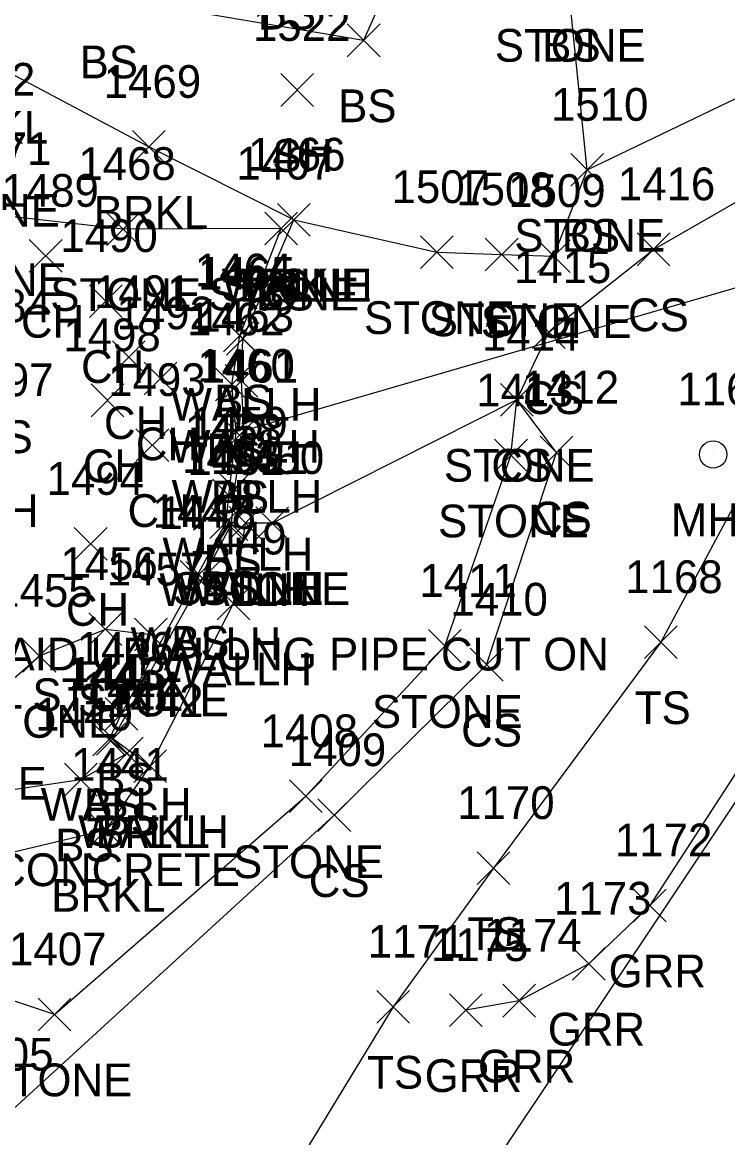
# Model space of a CAD drawing. Extents: x 1599840 to 1601211, y 518904 to 521989.
# Drawn here: x 1600771.9 to 1600815, y 521246 to 521314.2 of the extents above; entities that cross this region are included whole.
import ezdxf

# ---------------------------------------------------------------- set-up
doc = ezdxf.new("R2010")
doc.units = 0
for name, color, linetype in [('D_A', 7, 'Continuous'), ('D_C', 7, 'Continuous'), ('D_I', 7, 'Continuous'), ('D_TIC', 7, 'Continuous'), ('DCP', 7, 'Continuous'), ('DHW', 7, 'Continuous'), ('L_A', 7, 'Continuous'), ('L_C', 7, 'Continuous'), ('L_I', 7, 'Continuous'), ('L_TIC', 7, 'Continuous'), ('LASF', 7, 'Continuous'), ('LAWE', 7, 'Continuous'), ('LELB', 7, 'Continuous'), ('PET', 7, 'Continuous'), ('R_A', 7, 'Continuous'), ('R_I', 7, 'Continuous'), ('R_TIC', 7, 'Continuous'), ('RGR', 7, 'Continuous'), ('U_A', 7, 'Continuous'), ('U_I', 7, 'Continuous'), ('USMH', 7, 'Continuous')]:
    doc.layers.add(name, color=color, linetype=linetype)

msp = doc.modelspace()

# ---------------------------------------------------------------- linework, layer by layer
at = {"layer": 'D_TIC'}
for points in [[(1600787.504, 521301.133), (1600789.504, 521303.133)], [(1600789.504, 521301.133), (1600787.504, 521303.133)], [(1600784.387, 521293.849), (1600786.387, 521295.849)], [(1600786.387, 521293.849), (1600784.387, 521295.849)], [(1600784.3, 521291.284), (1600786.3, 521293.284)], [(1600786.3, 521291.284), (1600784.3, 521293.284)], [(1600784.444, 521288.23), (1600786.444, 521290.23)], [(1600786.444, 521288.23), (1600784.444, 521290.23)], [(1600784.444, 521288.23), (1600786.444, 521290.23)], [(1600786.444, 521288.23), (1600784.444, 521290.23)], [(1600783.887, 521284.699), (1600785.887, 521286.699)], [(1600785.887, 521284.699), (1600783.887, 521286.699)], [(1600783.695, 521282.537), (1600785.695, 521284.537)], [(1600785.695, 521282.537), (1600783.695, 521284.537)], [(1600784.559, 521282.602), (1600786.559, 521284.602)], [(1600786.559, 521282.602), (1600784.559, 521284.602)], [(1600781.935, 521279.231), (1600783.935, 521281.231)], [(1600783.935, 521279.231), (1600781.935, 521281.231)], [(1600783.815, 521277.679), (1600785.815, 521279.679)], [(1600785.815, 521277.679), (1600783.815, 521279.679)], [(1600776.448, 521269.418), (1600778.448, 521271.418)], [(1600778.448, 521269.418), (1600776.448, 521271.418)], [(1600778.729, 521267.746), (1600780.729, 521269.746)], [(1600780.729, 521267.746), (1600778.729, 521269.746)], [(1600778.729, 521267.746), (1600780.729, 521269.746)], [(1600780.729, 521267.746), (1600778.729, 521269.746)]]:
    msp.add_lwpolyline(points, dxfattribs=at)
at = {"layer": 'DCP'}
msp.add_lwpolyline([(1600954.732, 521338.43), (1600785.444, 521289.23)], dxfattribs=at)
at = {"layer": 'DHW'}
for points in [[(1600779.729, 521268.746), (1600777.448, 521270.418), (1600782.935, 521280.231), (1600784.695, 521283.537), (1600784.887, 521285.699), (1600785.444, 521289.23), (1600785.3, 521292.284), (1600785.387, 521294.849), (1600788.504, 521302.133)], [(1600779.729, 521268.746), (1600784.815, 521278.679), (1600785.559, 521283.602)]]:
    msp.add_lwpolyline(points, dxfattribs=at)
at = {"layer": 'L_TIC'}
for points in [[(1600791.769, 521312.092), (1600793.769, 521314.092)], [(1600793.769, 521312.092), (1600791.769, 521314.092)], [(1600787.702, 521309.057), (1600789.702, 521311.057)], [(1600789.702, 521309.057), (1600787.702, 521311.057)], [(1600778.639, 521305.578), (1600780.639, 521307.578)], [(1600780.639, 521305.578), (1600778.639, 521307.578)], [(1600805.428, 521304.176), (1600807.428, 521306.176)], [(1600807.428, 521304.176), (1600805.428, 521306.176)], [(1600805.428, 521304.176), (1600807.428, 521306.176)], [(1600807.428, 521304.176), (1600805.428, 521306.176)], [(1600787.504, 521301.133), (1600789.504, 521303.133)], [(1600789.504, 521301.133), (1600787.504, 521303.133)], [(1600787.504, 521301.133), (1600789.504, 521303.133)], [(1600789.504, 521301.133), (1600787.504, 521303.133)], [(1600777.08, 521300.561), (1600779.08, 521302.561)], [(1600779.08, 521300.561), (1600777.08, 521302.561)], [(1600786.733, 521300.588), (1600788.733, 521302.588)], [(1600788.733, 521300.588), (1600786.733, 521302.588)], [(1600786.733, 521300.588), (1600788.733, 521302.588)], [(1600788.733, 521300.588), (1600786.733, 521302.588)], [(1600772.345, 521298.923), (1600774.345, 521300.923)], [(1600774.345, 521298.923), (1600772.345, 521300.923)], [(1600796.248, 521299.149), (1600798.248, 521301.149)], [(1600798.248, 521299.149), (1600796.248, 521301.149)], [(1600800.203, 521299.015), (1600802.203, 521301.015)], [(1600802.203, 521299.015), (1600800.203, 521301.015)], [(1600803.381, 521298.912), (1600805.381, 521300.912)], [(1600805.381, 521298.912), (1600803.381, 521300.912)], [(1600809.479, 521299.323), (1600811.479, 521301.323)], [(1600811.479, 521299.323), (1600809.479, 521301.323)], [(1600776.018, 521296.16), (1600778.018, 521298.16)], [(1600778.018, 521296.16), (1600776.018, 521298.16)], [(1600803.075, 521294.258), (1600805.075, 521296.258)], [(1600805.075, 521294.258), (1600803.075, 521296.258)], [(1600784.198, 521294.053), (1600786.198, 521296.053)], [(1600786.198, 521294.053), (1600784.198, 521296.053)], [(1600777.417, 521292.732), (1600779.417, 521294.732)], [(1600779.417, 521292.732), (1600777.417, 521294.732)], [(1600779.364, 521291.436), (1600781.364, 521293.436)], [(1600781.364, 521291.436), (1600779.364, 521293.436)], [(1600783.719, 521291.066), (1600785.719, 521293.066)], [(1600785.719, 521291.066), (1600783.719, 521293.066)], [(1600776.119, 521290.098), (1600778.119, 521292.098)], [(1600778.119, 521290.098), (1600776.119, 521292.098)], [(1600801.128, 521290.126), (1600803.128, 521292.126)], [(1600803.128, 521290.126), (1600801.128, 521292.126)], [(1600801.128, 521290.126), (1600803.128, 521292.126)], [(1600803.128, 521290.126), (1600801.128, 521292.126)], [(1600783.988, 521288.181), (1600785.988, 521290.181)], [(1600785.988, 521288.181), (1600783.988, 521290.181)], [(1600778.858, 521287.36), (1600780.858, 521289.36)], [(1600780.858, 521287.36), (1600778.858, 521289.36)], [(1600800.771, 521286.725), (1600802.771, 521288.725)], [(1600802.771, 521286.725), (1600800.771, 521288.725)], [(1600803.556, 521286.901), (1600805.556, 521288.901)], [(1600805.556, 521286.901), (1600803.556, 521288.901)], [(1600783.535, 521284.275), (1600785.535, 521286.275)], [(1600785.535, 521284.275), (1600783.535, 521286.275)], [(1600783.373, 521282.656), (1600785.373, 521284.656)], [(1600785.373, 521282.656), (1600783.373, 521284.656)], [(1600784.559, 521282.602), (1600786.559, 521284.602)], [(1600786.559, 521282.602), (1600784.559, 521284.602)], [(1600786.187, 521282.594), (1600788.187, 521284.594)], [(1600788.187, 521282.594), (1600786.187, 521284.594)], [(1600775.092, 521281.323), (1600777.092, 521283.323)], [(1600777.092, 521281.323), (1600775.092, 521283.323)], [(1600781.563, 521279.311), (1600783.563, 521281.311)], [(1600783.563, 521279.311), (1600781.563, 521281.311)], [(1600775.99, 521276.111), (1600777.99, 521278.111)], [(1600777.99, 521276.111), (1600775.99, 521278.111)], [(1600778.773, 521275.79), (1600780.773, 521277.79)], [(1600780.773, 521275.79), (1600778.773, 521277.79)], [(1600796.728, 521275.088), (1600798.728, 521277.088)], [(1600798.728, 521275.088), (1600796.728, 521277.088)], [(1600809.924, 521275.319), (1600811.924, 521277.319)], [(1600811.924, 521275.319), (1600809.924, 521277.319)], [(1600771.957, 521274.482), (1600773.957, 521276.482)], [(1600773.957, 521274.482), (1600771.957, 521276.482)], [(1600799.284, 521273.946), (1600801.284, 521275.946)], [(1600801.284, 521273.946), (1600799.284, 521275.946)], [(1600776.984, 521270.944), (1600778.984, 521272.944)], [(1600778.984, 521270.944), (1600776.984, 521272.944)], [(1600776.22, 521269.369), (1600778.22, 521271.369)], [(1600778.22, 521269.369), (1600776.22, 521271.369)], [(1600777.299, 521268.516), (1600779.299, 521270.516)], [(1600779.299, 521268.516), (1600777.299, 521270.516)], [(1600778.729, 521267.746), (1600780.729, 521269.746)], [(1600780.729, 521267.746), (1600778.729, 521269.746)], [(1600774.487, 521266.923), (1600776.487, 521268.923)], [(1600776.487, 521266.923), (1600774.487, 521268.923)], [(1600788.245, 521265.906), (1600790.245, 521267.906)], [(1600790.245, 521265.906), (1600788.245, 521267.906)], [(1600789.977, 521264.75), (1600791.977, 521266.75)], [(1600791.977, 521264.75), (1600789.977, 521266.75)], [(1600776.034, 521263.853), (1600778.034, 521265.853)], [(1600778.034, 521263.853), (1600776.034, 521265.853)], [(1600799.695, 521261.518), (1600801.695, 521263.518)], [(1600801.695, 521261.518), (1600799.695, 521263.518)], [(1600772.881, 521252.578), (1600774.881, 521254.578)], [(1600774.881, 521252.578), (1600772.881, 521254.578)], [(1600772.881, 521252.578), (1600774.881, 521254.578)], [(1600774.881, 521252.578), (1600772.881, 521254.578)], [(1600793.575, 521253.044), (1600795.575, 521255.044)], [(1600795.575, 521253.044), (1600793.575, 521255.044)]]:
    msp.add_lwpolyline(points, dxfattribs=at)
at = {"layer": 'LASF'}
for points in [[(1600788.504, 521302.133), (1600797.248, 521300.149), (1600801.203, 521300.015), (1600804.381, 521299.912), (1600806.428, 521305.176), (1600805.239, 521316.786), (1600796.978, 521329.204), (1600794.865, 521329.922), (1600789.19, 521328.403), (1600773.997, 521324.831), (1600760.497, 521319.404), (1600745.632, 521315.291), (1600743.26, 521323.098), (1600732.014, 521314.218), (1600727.669, 521298.755)], [(1600787.733, 521301.588), (1600778.08, 521301.561), (1600769.876, 521302.473), (1600769.452, 521306.712), (1600761.198, 521309.066), (1600753.437, 521305.807), (1600746.621, 521300.165), (1600732.332, 521294.559), (1600731.017, 521295.657), (1600727.669, 521298.755)], [(1600773.881, 521253.578), (1600789.245, 521266.906), (1600797.728, 521276.088), (1600801.771, 521287.725), (1600802.128, 521291.126), (1600787.187, 521283.594), (1600785.559, 521283.602)], [(1600773.881, 521253.578), (1600761.877, 521257.582), (1600761.441, 521259.849), (1600764.145, 521267.439), (1600768.657, 521271.705), (1600772.957, 521275.482), (1600776.99, 521277.111), (1600779.773, 521276.79)]]:
    msp.add_lwpolyline(points, dxfattribs=at)
at = {"layer": 'LAWE'}
for points in [[(1600788.504, 521302.133), (1600779.639, 521306.578), (1600769.853, 521311.777), (1600761.009, 521310.636), (1600751.785, 521307.227), (1600745.14, 521302.726), (1600731.017, 521295.657), (1600729.255, 521276.143), (1600716.099, 521262.819), (1600704.876, 521257.404), (1600692.678, 521234.473)], [(1600710.084, 521218.612), (1600728.191, 521240.002), (1600744.345, 521252.061), (1600761.877, 521257.582), (1600767.454, 521262.572), (1600777.034, 521264.853), (1600779.729, 521268.746)]]:
    msp.add_lwpolyline(points, dxfattribs=at)
at = {"layer": 'LELB'}
for points in [[(1600796.978, 521329.204), (1600795.834, 521320.03), (1600792.769, 521313.092), (1600776.979, 521315.771), (1600787.857, 521318.753), (1600792.84, 521323.569), (1600794.865, 521329.922)], [(1600806.428, 521305.176), (1600817.079, 521310.295), (1600825.263, 521317.394), (1600823.051, 521319.829), (1600819.351, 521326.934), (1600812.796, 521319.539), (1600805.239, 521316.786)], [(1600833.084, 521322.836), (1600827.139, 521306.559), (1600810.924, 521276.319), (1600800.695, 521262.518), (1600794.575, 521254.044), (1600785.727, 521239.523), (1600767.248, 521213.824), (1600747.487, 521193.493), (1600721.354, 521163.12)], [(1600741.132, 521196.942), (1600761.003, 521225.763), (1600770.642, 521247.145), (1600790.977, 521265.75), (1600800.284, 521274.946), (1600804.556, 521287.901), (1600802.128, 521291.126), (1600804.075, 521295.258), (1600810.479, 521300.323), (1600825.075, 521308.704)], [(1600708.733, 521220.076), (1600727.282, 521240.92), (1600743.422, 521252.915), (1600761.441, 521259.849), (1600767.997, 521266.834), (1600775.487, 521267.923), (1600778.299, 521269.516), (1600777.22, 521270.369), (1600777.984, 521271.944), (1600782.563, 521280.311), (1600784.373, 521283.656), (1600784.535, 521285.275), (1600784.988, 521289.181), (1600784.719, 521292.066), (1600785.198, 521295.053), (1600787.733, 521301.588)]]:
    msp.add_lwpolyline(points, dxfattribs=at)
at = {"layer": 'PET'}
msp.add_lwpolyline([(1600925.829, 521507.518), (1600915.18, 521473.309), (1600903.262, 521440.284), (1600887.481, 521401.444), (1600873.353, 521370.155), (1600860.378, 521343.642), (1600847.931, 521319.686), (1600844.651, 521313.138), (1600836.724, 521299.896), (1600818.79, 521271.507), (1600793.687, 521233.92), (1600774.487, 521208.057), (1600757.089, 521185.54), (1600730.915, 521154.494)], dxfattribs=at)
at = {"layer": 'R_TIC'}
for points in [[(1600809.245, 521259.238), (1600811.245, 521261.238)], [(1600811.245, 521259.238), (1600809.245, 521261.238)], [(1600805.532, 521255.677), (1600807.532, 521257.677)], [(1600807.532, 521255.677), (1600805.532, 521257.677)], [(1600801.263, 521253.419), (1600803.263, 521255.419)], [(1600803.263, 521253.419), (1600801.263, 521255.419)], [(1600798.012, 521252.838), (1600800.012, 521254.838)], [(1600800.012, 521252.838), (1600798.012, 521254.838)]]:
    msp.add_lwpolyline(points, dxfattribs=at)
at = {"layer": 'RGR'}
msp.add_lwpolyline([(1600826.087, 521344.206), (1600833.693, 521339.744), (1600838.119, 521335.633), (1600842.433, 521329.401), (1600844.673, 521324.013), (1600844.997, 521318.731), (1600843.514, 521313.735), (1600835.628, 521300.635), (1600817.836, 521271.897), (1600810.245, 521260.238), (1600806.532, 521256.677), (1600802.263, 521254.419), (1600799.012, 521253.838)], dxfattribs=at)
at = {"layer": 'USMH'}
for p, q in [((1600814.12, 521287.795), (1600814.12, 521287.795)), ((1600814.953, 521287.795), (1600814.953, 521287.795))]:
    msp.add_line(p, q, dxfattribs=at)
msp.add_circle((1600814.12, 521287.795), 0.833, dxfattribs=at)

# ---------------------------------------------------------------- texts
at = {"layer": 'D_A'}
for s, p in [('WALLH', (1600784.095, 521297.133)), ('WALLH', (1600780.977, 521289.849)), ('WALLH', (1600780.89, 521287.284)), ('WALLH', (1600781.034, 521284.23)), ('P', (1600784.822, 521284.23)), ('WALLH', (1600780.478, 521280.699)), ('WALLH', (1600780.286, 521278.537)), ('WALLH', (1600781.15, 521278.602)), ('WALLH', (1600778.526, 521275.231)), ('WALLH', (1600780.406, 521273.679)), ('WALLH', (1600773.039, 521265.418)), ('WALLH', (1600775.319, 521263.746)), ('WALLH', (1600775.319, 521263.746))]:
    msp.add_text(s, height=2, dxfattribs=at).set_placement(p)
at = {"layer": 'D_C'}
msp.add_text('CONCRETE', height=2, dxfattribs=at).set_placement((1600770.204, 521261.418))
at = {"layer": 'D_I'}
for s, p in [('1466', (1600785.709, 521305.133)), ('1465', (1600782.647, 521297.849)), ('1463', (1600782.56, 521295.284)), ('1460', (1600782.617, 521292.23)), ('1460', (1600782.617, 521292.23)), ('1459', (1600782.186, 521288.699)), ('1451', (1600783.433, 521286.602)), ('1452', (1600782.003, 521286.537)), ('1448', (1600780.242, 521283.231)), ('1449', (1600782.115, 521281.679)), ('1443', (1600774.755, 521273.418)), ('1442', (1600777.036, 521271.746)), ('1442', (1600777.036, 521271.746))]:
    msp.add_text(s, height=2, dxfattribs=at).set_placement(p)
at = {"layer": 'L_A'}
for s, p in [('BS', (1600786.298, 521313.753)), ('STONE', (1600800.782, 521311.786)), ('BS', (1600803.679, 521311.786)), ('BS', (1600775.42, 521310.771)), ('BS', (1600791.21, 521308.092)), ('BRKL', (1600766.499, 521306.777)), ('SH', (1600787.19, 521305.057)), ('STONE', (1600764.996, 521301.712)), ('BRKL', (1600776.285, 521301.578)), ('STONE', (1600801.971, 521300.176)), ('BS', (1600804.869, 521300.176)), ('STONE', (1600765.419, 521297.473)), ('STONE', (1600784.048, 521297.133)), ('BRKL', (1600785.15, 521297.133)), ('STONE', (1600773.623, 521296.561)), ('STONE', (1600783.277, 521296.588)), ('BS', (1600786.174, 521296.588)), ('CH', (1600771.833, 521294.923)), ('STONE', (1600792.791, 521295.149)), ('STONE', (1600796.746, 521295.015)), ('STONE', (1600799.925, 521294.912)), ('CS', (1600808.92, 521295.323)), ('CH', (1600775.507, 521292.16)), ('BS', (1600783.639, 521290.053)), ('CS', (1600802.516, 521290.258)), ('CH', (1600776.905, 521288.732)), ('CS', (1600768.84, 521287.873)), ('CH', (1600778.853, 521287.436)), ('BS', (1600783.16, 521287.066)), ('CH', (1600775.607, 521286.098)), ('STONE', (1600797.671, 521286.126)), ('CS', (1600800.568, 521286.126)), ('BS', (1600783.429, 521284.181)), ('CH', (1600769.057, 521283.355)), ('CH', (1600778.346, 521283.36)), ('STONE', (1600797.314, 521282.725)), ('CS', (1600802.997, 521282.901)), ('BS', (1600782.976, 521280.275)), ('STONE', (1600781.102, 521278.602)), ('STONE', (1600782.73, 521278.594)), ('BS', (1600782.814, 521278.656)), ('CH', (1600774.58, 521277.323)), ('BS', (1600781.004, 521275.311)), ('STONE', (1600772.533, 521272.111)), ('STONE', (1600775.316, 521271.79)), ('STONE', (1600793.272, 521271.088)), ('TS', (1600809.333, 521271.319)), ('STONE', (1600768.5, 521270.482)), ('CS', (1600798.725, 521269.946)), ('BS', (1600776.425, 521266.944)), ('STONE', (1600764.2, 521266.705)), ('BS', (1600775.661, 521265.369)), ('BS', (1600776.74, 521264.516)), ('BRKL', (1600776.374, 521263.746)), ('BS', (1600773.928, 521262.923)), ('STONE', (1600784.789, 521261.906)), ('CS', (1600789.418, 521260.75)), ('BRKL', (1600773.679, 521259.853)), ('TS', (1600799.104, 521257.518)), ('STONE', (1600769.424, 521248.578)), ('STONE', (1600769.424, 521248.578)), ('TS', (1600792.985, 521249.044))]:
    msp.add_text(s, height=2, dxfattribs=at).set_placement(p)
at = {"layer": 'L_C'}
msp.add_text('STONE LAID UP ALONG PIPE CUT ON', height=2, dxfattribs=at).set_placement((1600759.447, 521274.594))
at = {"layer": 'L_I'}
for s, p in [('1522', (1600786.009, 521313.057)), ('1472', (1600766.76, 521309.712)), ('1469', (1600776.892, 521309.578)), ('1510', (1600804.215, 521308.176)), ('1510', (1600804.215, 521308.176)), ('1471', (1600767.75, 521305.473)), ('1466', (1600785.709, 521305.133)), ('1466', (1600785.709, 521305.133)), ('1468', (1600775.34, 521304.561)), ('1467', (1600784.993, 521304.588)), ('1467', (1600784.993, 521304.588)), ('1489', (1600770.644, 521302.923)), ('1507', (1600794.477, 521303.149)), ('1508', (1600798.432, 521303.015)), ('1509', (1600801.602, 521302.912)), ('1416', (1600808.298, 521303.323)), ('1490', (1600774.239, 521300.16)), ('1415', (1600801.95, 521298.258)), ('1464', (1600782.458, 521298.053)), ('1491', (1600776.291, 521296.732)), ('1484', (1600767.706, 521295.873)), ('1492', (1600777.672, 521295.436)), ('1462', (1600781.979, 521295.066)), ('1498', (1600774.426, 521294.098)), ('1414', (1600800.002, 521294.126)), ('1414', (1600800.002, 521294.126)), ('1461', (1600782.815, 521292.181)), ('1497', (1600767.876, 521291.355)), ('1493', (1600777.165, 521291.36)), ('1413', (1600799.645, 521290.725)), ('1412', (1600802.431, 521290.901)), ('1458', (1600781.842, 521288.275)), ('1453', (1600781.68, 521286.656)), ('1451', (1600783.433, 521286.602)), ('1450', (1600784.408, 521286.594)), ('1494', (1600773.399, 521285.323)), ('1447', (1600779.87, 521283.311)), ('1456', (1600774.242, 521280.111)), ('1457', (1600777.08, 521279.79)), ('1411', (1600796.17, 521279.088)), ('1168', (1600808.751, 521279.319)), ('1455', (1600770.264, 521278.482)), ('1410', (1600798.072, 521277.946)), ('1446', (1600775.236, 521274.944)), ('1445', (1600774.527, 521273.369)), ('1444', (1600775.607, 521272.516)), ('1442', (1600777.036, 521271.746)), ('1440', (1600772.707, 521270.923)), ('1408', (1600786.474, 521269.906)), ('1409', (1600788.197, 521268.75)), ('1441', (1600774.908, 521267.853)), ('1170', (1600798.483, 521265.518)), ('1407', (1600771.109, 521256.578)), ('1407', (1600771.109, 521256.578)), ('1171', (1600793.017, 521257.044)), ('1405', (1600767.871, 521250.145))]:
    msp.add_text(s, height=2, dxfattribs=at).set_placement(p)
at = {"layer": 'R_A'}
for p in [(1600807.733, 521255.238), (1600804.021, 521251.677), (1600799.751, 521249.419), (1600796.5, 521248.838)]:
    msp.add_text('GRR', height=2, dxfattribs=at).set_placement(p)
at = {"layer": 'R_I'}
for s, p in [('1172', (1600808.119, 521263.238)), ('1173', (1600804.407, 521259.677)), ('1174', (1600800.137, 521257.419)), ('1175', (1600796.887, 521256.838))]:
    msp.add_text(s, height=2, dxfattribs=at).set_placement(p)
at = {"layer": 'U_A'}
msp.add_text('MHS', height=2, dxfattribs=at).set_placement((1600811.537, 521282.795))
at = {"layer": 'U_I'}
msp.add_text('1169', height=2, dxfattribs=at).set_placement((1600811.939, 521290.795))

doc.saveas('drawing.dxf')
